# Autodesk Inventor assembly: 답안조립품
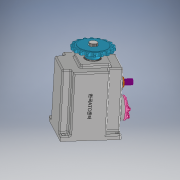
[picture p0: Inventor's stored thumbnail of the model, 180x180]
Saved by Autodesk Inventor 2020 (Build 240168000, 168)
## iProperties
Created: 2022-01
Part Number: 답안조립품
Document SubType Name: Assembly
Designer: user
Author: user
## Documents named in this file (16)
- C:\Users\user\Desktop\720112V1004\답안조립품.iam
- C:\Users\user\Desktop\720112V1004\멈춤나사 M3.ipt
- C:\Users\user\Desktop\720112V1004\메인 축.ipt
- C:\Users\user\Desktop\720112V1004\베어링 608.ipt
- C:\Users\user\Desktop\720112V1004\베어링 6003.ipt
- C:\Users\user\Desktop\720112V1004\본체.ipt
- C:\Users\user\Desktop\720112V1004\볼트 M4 x 10.ipt
- C:\Users\user\Desktop\720112V1004\부시.ipt
- C:\Users\user\Desktop\720112V1004\상부 캡.ipt
- C:\Users\user\Desktop\720112V1004\서브 축.ipt
- C:\Users\user\Desktop\720112V1004\스프로킷.ipt
- C:\Users\user\Desktop\720112V1004\슬라이더.ipt
- C:\Users\user\Desktop\720112V1004\오일 실 8 x 22 x 7.ipt
- C:\Users\user\Desktop\720112V1004\오일 실 17 x 32 x 8.ipt
- C:\Users\user\Desktop\720112V1004\커버.ipt
- C:\Users\user\Desktop\720112V1004\키 5 x 5.ipt
